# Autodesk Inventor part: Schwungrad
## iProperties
Created: 2003-12
Part Number: Schwungrad
Material: Messing (weiches, gelbes Messing)
Document SubType Name: Modellieren
Designer: Ulrich
Control State: 0
Master: False
Checked Out: False
Shininess: 20.0
Angle Display Precision: 2
Document Length Units: 11269
Document Angle Units: 11279
Document Time Units: 11290
Document Mass Units: 11283
Document Length Units Precision: 3
Document Angle Units Precision: 2
Density: 0.0
Volumn: 0.0
Area: 0.0
PropertySet Name: Model Information
Author: Ulrich
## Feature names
1. Drehung [Revolution]
2. Achsbohrung [Hole]
3. Kurbelzapfenbohrung [Hole]
4. Aussparung [Extrusion]
5. Rundung_Aussparung [Fillet]
6. Rundung_Grundkörper [Fillet]
